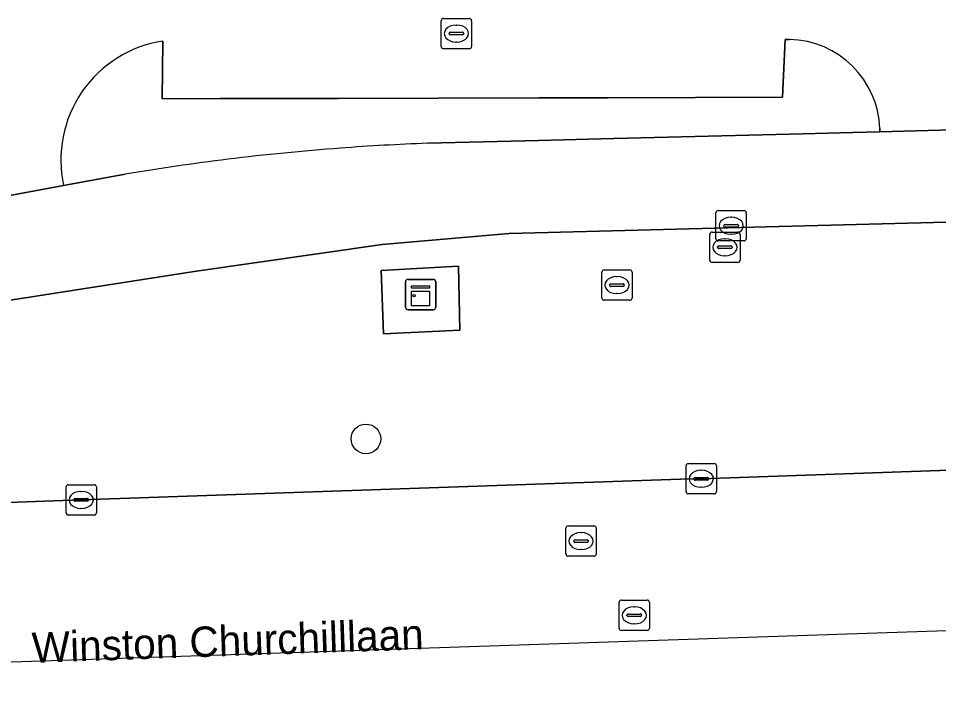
# Model space of a CAD drawing. Extents: x 160888 to 161385, y 386490 to 386908.
# Drawn here: x 161111.03 to 161141.39, y 386494.25 to 386516.39 of the extents above; entities that cross this region are included whole.
import ezdxf

# ---------------------------------------------------------------- set-up
doc = ezdxf.new("R2010")
doc.units = 0
for name, color, linetype in [('IMGEO_Berm_groen', 7, 'Continuous'), ('IMGEO_Boom', 7, 'Continuous'), ('IMGEO_Fietspad_gesloten', 7, 'Continuous'), ('IMGEO_Groenvoorziening', 7, 'Continuous'), ('IMGEO_Kast', 7, 'Continuous'), ('IMGEO_Kolk', 7, 'Continuous'), ('IMGEO_Openbare_ruimte_label', 7, 'Continuous'), ('IMGEO_Rijbaan_regionaal_gesloten', 7, 'Continuous'), ('IMGEO_Rioolput', 7, 'Continuous'), ('IMGEO_Voetgangersgebied_open', 7, 'Continuous'), ('IMGEO_Voetpad_open', 7, 'Continuous')]:
    doc.layers.add(name, color=color, linetype=linetype)

msp = doc.modelspace()

# ---------------------------------------------------------------- linework, layer by layer
at = {"layer": 'IMGEO_Berm_groen'}
msp.add_lwpolyline([(161167.964, 386510.348), (161127.225, 386509.29), (161123.035, 386508.931), (161116.836, 386508.035), (161109.839, 386506.955), (161110.084, 386500.399), (161113.106, 386500.507), (161132.874, 386501.189), (161133.563, 386501.204), (161154.024, 386501.918)], dxfattribs=at)
msp.add_lwpolyline([(161123.077, 386505.983), (161123.003, 386508.068), (161125.558, 386508.215), (161125.6, 386506.109)], close=True, dxfattribs=at)
at = {"layer": 'IMGEO_Boom'}
msp.add_circle((161122.501, 386502.519), 0.489, dxfattribs=at)
at = {"layer": 'IMGEO_Fietspad_gesloten'}
for points in [[(161142.637, 386512.729), (161139.461, 386512.648), (161138.561, 386512.625), (161136.913, 386512.583), (161130.684, 386512.424), (161128.205, 386512.361), (161124.527, 386512.267)], [(161106.833, 386506.491), (161109.839, 386506.955), (161116.836, 386508.035), (161123.035, 386508.931), (161127.225, 386509.29), (161167.964, 386510.348), (161215.734, 386511.569), (161215.758, 386511.159), (161222.805, 386511.284), (161237.753, 386511.488), (161259.697, 386511.429), (161267.164, 386511.376), (161306.097, 386509.668), (161311.73, 386509.285), (161311.776, 386509.705), (161313.071, 386509.592)], [(161114.554, 386511.246), (161112.524, 386510.872), (161110.624, 386510.522), (161110.357, 386510.473), (161109.295, 386510.286), (161107.767, 386510.044)]]:
    msp.add_lwpolyline(points, dxfattribs=at)
for centre, radius, start, end in [((161127.309, 386436.217), 76.101, 92.09478, 94.25602), ((161127.324, 386435.906), 76.412, 94.24984, 97.05235), ((161127.239, 386436.116), 76.193, 97.00834, 99.58319)]:
    msp.add_arc(centre, radius, start, end, dxfattribs=at)
at = {"layer": 'IMGEO_Groenvoorziening'}
for points in [[(161136.477, 386515.69), (161136.328, 386515.689), (161136.246, 386513.784), (161130.488, 386513.771), (161128.205, 386513.766), (161121.578, 386513.75), (161117.674, 386513.741), (161115.774, 386513.737), (161115.797, 386515.64)], [(161124.527, 386512.267), (161128.205, 386512.361), (161130.684, 386512.424), (161136.913, 386512.583), (161138.561, 386512.625), (161139.461, 386512.648)], [(161139.461, 386512.648), (161139.456, 386512.756)], [(161112.524, 386510.872), (161114.554, 386511.246)]]:
    msp.add_lwpolyline(points, dxfattribs=at)
for centre, radius, start, end in [((161116.404, 386511.716), 3.971, 98.7933, 192.2713), ((161136.411, 386512.644), 3.047, 2.1139, 88.7582), ((161127.309, 386436.217), 76.101, 92.09478, 94.25602), ((161127.324, 386435.906), 76.412, 94.24984, 97.05235), ((161127.239, 386436.116), 76.193, 97.00834, 99.58319)]:
    msp.add_arc(centre, radius, start, end, dxfattribs=at)
at = {"layer": 'IMGEO_Kast'}
for p, q in [((161123.804, 386506.855), (161123.804, 386507.696)), ((161123.804, 386507.696), (161123.804, 386506.855)), ((161123.879, 386507.78), (161124.72, 386507.78)), ((161124.72, 386507.78), (161123.879, 386507.78)), ((161124.804, 386507.705), (161124.804, 386506.864)), ((161124.804, 386506.864), (161124.804, 386507.705)), ((161124.729, 386506.78), (161123.888, 386506.78)), ((161123.888, 386506.78), (161124.729, 386506.78))]:
    msp.add_line(p, q, dxfattribs=at)
for points in [[(161123.999, 386507.57), (161124.599, 386507.57), (161124.599, 386507.485), (161123.999, 386507.485), (161123.999, 386507.57)], [(161123.999, 386507.395), (161124.599, 386507.395), (161124.599, 386506.906), (161123.999, 386506.906), (161123.999, 386507.395)]]:
    msp.add_lwpolyline(points, dxfattribs=at)
msp.add_circle((161124.083, 386507.244), 0.0377, dxfattribs=at)
for centre, start, end in [((161123.882, 386507.702), 92.4484, 184.2845), ((161123.882, 386507.702), 92.4484, 184.2845), ((161124.726, 386507.702), 2.4484, 94.2845), ((161124.726, 386507.702), 2.4484, 94.2845), ((161123.882, 386506.858), 182.4484, 274.2845), ((161123.882, 386506.858), 182.4484, 274.2845), ((161124.726, 386506.858), 272.4484, 4.2845), ((161124.726, 386506.858), 272.4484, 4.2845)]:
    msp.add_arc(centre, 0.0779, start, end, dxfattribs=at)
at = {"layer": 'IMGEO_Kolk'}
for p, q in [((161124.985, 386515.46), (161124.985, 386516.312)), ((161125.06, 386516.386), (161125.912, 386516.386)), ((161125.473, 386516.166), (161125.498, 386516.166)), ((161125.986, 386516.312), (161125.986, 386515.46)), ((161125.244, 386515.88), (161125.244, 386515.892)), ((161125.682, 386515.843), (161125.284, 386515.843)), ((161125.287, 386515.929), (161125.685, 386515.929)), ((161125.728, 386515.892), (161125.728, 386515.88)), ((161125.496, 386515.606), (161125.471, 386515.606)), ((161125.912, 386515.386), (161125.06, 386515.386)), ((161133.062, 386500.778), (161133.062, 386501.63)), ((161133.137, 386501.704), (161133.989, 386501.704)), ((161134.063, 386501.63), (161134.063, 386500.778)), ((161133.364, 386501.247), (161133.762, 386501.247)), ((161133.55, 386501.484), (161133.575, 386501.484)), ((161112.605, 386500.081), (161112.605, 386500.933)), ((161112.68, 386501.007), (161113.532, 386501.007)), ((161113.606, 386500.933), (161113.606, 386500.081)), ((161133.321, 386501.198), (161133.321, 386501.21)), ((161133.759, 386501.161), (161133.361, 386501.161)), ((161133.573, 386500.924), (161133.548, 386500.924)), ((161133.805, 386501.21), (161133.805, 386501.198)), ((161113.093, 386500.787), (161113.118, 386500.787)), ((161133.989, 386500.704), (161133.137, 386500.704)), ((161112.864, 386500.501), (161112.864, 386500.513)), ((161113.302, 386500.464), (161112.904, 386500.464)), ((161112.907, 386500.55), (161113.305, 386500.55)), ((161113.348, 386500.513), (161113.348, 386500.501)), ((161113.116, 386500.227), (161113.091, 386500.227)), ((161113.532, 386500.007), (161112.68, 386500.007))]:
    msp.add_line(p, q, dxfattribs=at)
for points in [[(161124.985, 386515.46), (161124.985, 386516.312)], [(161125.06, 386516.386), (161125.912, 386516.386)], [(161125.986, 386516.312), (161125.986, 386515.46)], [(161125.912, 386515.386), (161125.06, 386515.386)], [(161133.062, 386500.778), (161133.062, 386501.63)], [(161133.137, 386501.704), (161133.989, 386501.704)], [(161134.063, 386501.63), (161134.063, 386500.778)], [(161112.605, 386500.081), (161112.605, 386500.933)], [(161112.68, 386501.007), (161113.532, 386501.007)], [(161113.606, 386500.933), (161113.606, 386500.081)], [(161133.989, 386500.704), (161133.137, 386500.704)], [(161113.532, 386500.007), (161112.68, 386500.007)]]:
    msp.add_lwpolyline(points, dxfattribs=at)
for centre, radius, start, end in [((161125.062, 386516.31), 0.0765, 91.552, 178.448), ((161125.062, 386516.31), 0.0765, 91.552, 178.448), ((161125.91, 386516.31), 0.0765, 1.552, 88.448), ((161125.91, 386516.31), 0.0765, 1.552, 88.448), ((161125.284, 386515.889), 0.0403, 85.8775, 175.7526), ((161125.281, 386515.879), 0.0366, 178.938, 274.7102), ((161125.685, 386515.886), 0.043, 264.8664, 352.4533), ((161125.689, 386515.891), 0.0386, 1.7309, 96.639), ((161125.062, 386515.462), 0.0765, 181.552, 268.448), ((161125.062, 386515.462), 0.0765, 181.552, 268.448), ((161125.91, 386515.462), 0.0765, 271.552, 358.448), ((161125.91, 386515.462), 0.0765, 271.552, 358.448), ((161133.139, 386501.628), 0.0765, 91.552, 178.448), ((161133.139, 386501.628), 0.0765, 91.552, 178.448), ((161133.987, 386501.628), 0.0765, 1.552, 88.448), ((161133.987, 386501.628), 0.0765, 1.552, 88.448), ((161133.361, 386501.207), 0.0403, 85.8775, 175.7526), ((161133.766, 386501.209), 0.0386, 1.7309, 96.639), ((161112.682, 386500.931), 0.0765, 91.552, 178.448), ((161112.682, 386500.931), 0.0765, 91.552, 178.448), ((161113.53, 386500.931), 0.0765, 1.552, 88.448), ((161113.53, 386500.931), 0.0765, 1.552, 88.448), ((161133.358, 386501.197), 0.0366, 178.938, 274.7102), ((161133.762, 386501.204), 0.043, 264.8664, 352.4533), ((161133.139, 386500.78), 0.0765, 181.552, 268.448), ((161133.139, 386500.78), 0.0765, 181.552, 268.448), ((161133.987, 386500.78), 0.0765, 271.552, 358.448), ((161133.987, 386500.78), 0.0765, 271.552, 358.448), ((161112.904, 386500.51), 0.0403, 85.8775, 175.7526), ((161112.901, 386500.5), 0.0366, 178.938, 274.7102), ((161113.305, 386500.507), 0.043, 264.8664, 352.4533), ((161113.309, 386500.512), 0.0386, 1.7309, 96.639), ((161112.682, 386500.083), 0.0765, 181.552, 268.448), ((161112.682, 386500.083), 0.0765, 181.552, 268.448), ((161113.53, 386500.083), 0.0765, 271.552, 358.448), ((161113.53, 386500.083), 0.0765, 271.552, 358.448)]:
    msp.add_arc(centre, radius, start, end, dxfattribs=at)
for centre, major_axis, ratio, start_param, end_param in [((161125.472, 386515.886), (-0.387, 0.002), 0.722429, 4.712389, 7.853982), ((161125.497, 386515.886), (-0.39, 0.002), 0.717154, 1.570796, 4.712389), ((161133.549, 386501.204), (-0.387, 0.002), 0.722429, 4.712389, 7.853982), ((161133.574, 386501.204), (-0.39, 0.002), 0.717154, 1.570796, 4.712389), ((161113.092, 386500.507), (-0.387, 0.002), 0.722429, 4.712389, 7.853982), ((161113.117, 386500.507), (-0.39, 0.002), 0.717154, 1.570796, 4.712389)]:
    msp.add_ellipse(centre, major_axis=major_axis, ratio=ratio, start_param=start_param, end_param=end_param, dxfattribs=at)
at = {"layer": 'IMGEO_Rijbaan_regionaal_gesloten'}
for points in [[(161154.024, 386501.918), (161133.563, 386501.204), (161132.874, 386501.189), (161113.106, 386500.507), (161110.084, 386500.399), (161094.63, 386499.845), (161093.606, 386499.805), (161083.962, 386499.473), (161082.563, 386499.415), (161073.327, 386499.101), (161067.084, 386499.011), (161061.756, 386498.98)], [(161083.554, 386494.25), (161197.468, 386498.064)]]:
    msp.add_lwpolyline(points, dxfattribs=at)
at = {"layer": 'IMGEO_Rioolput'}
for p, q in [((161134.124, 386510.048), (161134.976, 386510.048)), ((161134.049, 386509.122), (161134.049, 386509.974)), ((161134.537, 386509.828), (161134.562, 386509.828)), ((161135.05, 386509.974), (161135.05, 386509.122)), ((161134.308, 386509.542), (161134.308, 386509.554)), ((161134.746, 386509.505), (161134.348, 386509.505)), ((161134.351, 386509.591), (161134.749, 386509.591)), ((161134.792, 386509.554), (161134.792, 386509.542)), ((161133.844, 386508.412), (161133.844, 386509.264)), ((161133.919, 386509.338), (161134.771, 386509.338)), ((161134.56, 386509.268), (161134.535, 386509.268)), ((161134.845, 386509.264), (161134.845, 386508.412)), ((161134.103, 386508.832), (161134.103, 386508.844)), ((161134.976, 386509.048), (161134.124, 386509.048)), ((161134.146, 386508.881), (161134.544, 386508.881)), ((161134.332, 386509.118), (161134.357, 386509.118)), ((161134.587, 386508.844), (161134.587, 386508.832)), ((161134.541, 386508.795), (161134.143, 386508.795)), ((161134.355, 386508.558), (161134.33, 386508.558)), ((161134.771, 386508.338), (161133.919, 386508.338)), ((161130.282, 386507.165), (161130.282, 386508.017)), ((161130.357, 386508.091), (161131.209, 386508.091)), ((161131.283, 386508.017), (161131.283, 386507.165)), ((161130.584, 386507.634), (161130.982, 386507.634)), ((161130.77, 386507.871), (161130.795, 386507.871)), ((161130.541, 386507.585), (161130.541, 386507.597)), ((161130.979, 386507.548), (161130.581, 386507.548)), ((161130.793, 386507.311), (161130.768, 386507.311)), ((161131.025, 386507.597), (161131.025, 386507.585)), ((161131.209, 386507.091), (161130.357, 386507.091)), ((161129.096, 386498.722), (161129.096, 386499.574)), ((161129.171, 386499.648), (161130.023, 386499.648)), ((161129.584, 386499.428), (161129.609, 386499.428)), ((161130.097, 386499.574), (161130.097, 386498.722)), ((161129.355, 386499.142), (161129.355, 386499.154)), ((161129.793, 386499.105), (161129.395, 386499.105)), ((161129.398, 386499.191), (161129.796, 386499.191)), ((161129.839, 386499.154), (161129.839, 386499.142)), ((161129.607, 386498.868), (161129.582, 386498.868)), ((161130.023, 386498.648), (161129.171, 386498.648)), ((161130.852, 386496.274), (161130.852, 386497.126)), ((161130.927, 386497.2), (161131.779, 386497.2)), ((161131.34, 386496.98), (161131.365, 386496.98)), ((161131.853, 386497.126), (161131.853, 386496.274)), ((161131.111, 386496.694), (161131.111, 386496.706)), ((161131.154, 386496.743), (161131.552, 386496.743)), ((161131.595, 386496.706), (161131.595, 386496.694)), ((161131.549, 386496.657), (161131.151, 386496.657)), ((161131.363, 386496.42), (161131.338, 386496.42)), ((161131.779, 386496.2), (161130.927, 386496.2))]:
    msp.add_line(p, q, dxfattribs=at)
for points in [[(161134.124, 386510.048), (161134.976, 386510.048)], [(161134.049, 386509.122), (161134.049, 386509.974)], [(161135.05, 386509.974), (161135.05, 386509.122)], [(161133.844, 386508.412), (161133.844, 386509.264)], [(161133.919, 386509.338), (161134.771, 386509.338)], [(161134.845, 386509.264), (161134.845, 386508.412)], [(161134.976, 386509.048), (161134.124, 386509.048)], [(161134.771, 386508.338), (161133.919, 386508.338)], [(161130.282, 386507.165), (161130.282, 386508.017)], [(161130.357, 386508.091), (161131.209, 386508.091)], [(161131.283, 386508.017), (161131.283, 386507.165)], [(161131.209, 386507.091), (161130.357, 386507.091)], [(161129.096, 386498.722), (161129.096, 386499.574)], [(161129.171, 386499.648), (161130.023, 386499.648)], [(161130.097, 386499.574), (161130.097, 386498.722)], [(161130.023, 386498.648), (161129.171, 386498.648)], [(161130.852, 386496.274), (161130.852, 386497.126)], [(161130.927, 386497.2), (161131.779, 386497.2)], [(161131.853, 386497.126), (161131.853, 386496.274)], [(161131.779, 386496.2), (161130.927, 386496.2)]]:
    msp.add_lwpolyline(points, dxfattribs=at)
for centre, radius, start, end in [((161134.126, 386509.972), 0.0765, 91.552, 178.448), ((161134.126, 386509.972), 0.0765, 91.552, 178.448), ((161134.974, 386509.972), 0.0765, 1.552, 88.448), ((161134.974, 386509.972), 0.0765, 1.552, 88.448), ((161134.348, 386509.551), 0.0403, 85.8775, 175.7526), ((161134.345, 386509.541), 0.0366, 178.938, 274.7102), ((161134.749, 386509.548), 0.043, 264.8664, 352.4533), ((161134.753, 386509.553), 0.0386, 1.7309, 96.639), ((161133.921, 386509.262), 0.0765, 91.552, 178.448), ((161133.921, 386509.262), 0.0765, 91.552, 178.448), ((161134.126, 386509.124), 0.0765, 181.552, 268.448), ((161134.126, 386509.124), 0.0765, 181.552, 268.448), ((161134.769, 386509.262), 0.0765, 1.552, 88.448), ((161134.769, 386509.262), 0.0765, 1.552, 88.448), ((161134.974, 386509.124), 0.0765, 271.552, 358.448), ((161134.974, 386509.124), 0.0765, 271.552, 358.448), ((161134.143, 386508.841), 0.0403, 85.8775, 175.7526), ((161134.14, 386508.831), 0.0366, 178.938, 274.7102), ((161134.544, 386508.838), 0.043, 264.8664, 352.4533), ((161134.548, 386508.843), 0.0386, 1.7309, 96.639), ((161133.921, 386508.414), 0.0765, 181.552, 268.448), ((161133.921, 386508.414), 0.0765, 181.552, 268.448), ((161134.769, 386508.414), 0.0765, 271.552, 358.448), ((161134.769, 386508.414), 0.0765, 271.552, 358.448), ((161130.359, 386508.015), 0.0765, 91.552, 178.448), ((161130.359, 386508.015), 0.0765, 91.552, 178.448), ((161131.207, 386508.015), 0.0765, 1.552, 88.448), ((161131.207, 386508.015), 0.0765, 1.552, 88.448), ((161130.581, 386507.594), 0.0403, 85.8775, 175.7526), ((161130.986, 386507.596), 0.0386, 1.7309, 96.639), ((161130.578, 386507.584), 0.0366, 178.938, 274.7102), ((161130.982, 386507.591), 0.043, 264.8664, 352.4533), ((161130.359, 386507.167), 0.0765, 181.552, 268.448), ((161130.359, 386507.167), 0.0765, 181.552, 268.448), ((161131.207, 386507.167), 0.0765, 271.552, 358.448), ((161131.207, 386507.167), 0.0765, 271.552, 358.448), ((161129.173, 386499.572), 0.0765, 91.552, 178.448), ((161129.173, 386499.572), 0.0765, 91.552, 178.448), ((161130.021, 386499.572), 0.0765, 1.552, 88.448), ((161130.021, 386499.572), 0.0765, 1.552, 88.448), ((161129.395, 386499.151), 0.0403, 85.8775, 175.7526), ((161129.392, 386499.141), 0.0366, 178.938, 274.7102), ((161129.796, 386499.148), 0.043, 264.8664, 352.4533), ((161129.8, 386499.153), 0.0386, 1.7309, 96.639), ((161129.173, 386498.724), 0.0765, 181.552, 268.448), ((161129.173, 386498.724), 0.0765, 181.552, 268.448), ((161130.021, 386498.724), 0.0765, 271.552, 358.448), ((161130.021, 386498.724), 0.0765, 271.552, 358.448), ((161130.929, 386497.124), 0.0765, 91.552, 178.448), ((161130.929, 386497.124), 0.0765, 91.552, 178.448), ((161131.777, 386497.124), 0.0765, 1.552, 88.448), ((161131.777, 386497.124), 0.0765, 1.552, 88.448), ((161131.151, 386496.703), 0.0403, 85.8775, 175.7526), ((161131.148, 386496.693), 0.0366, 178.938, 274.7102), ((161131.552, 386496.7), 0.043, 264.8664, 352.4533), ((161131.556, 386496.705), 0.0386, 1.7309, 96.639), ((161130.929, 386496.276), 0.0765, 181.552, 268.448), ((161130.929, 386496.276), 0.0765, 181.552, 268.448), ((161131.777, 386496.276), 0.0765, 271.552, 358.448), ((161131.777, 386496.276), 0.0765, 271.552, 358.448)]:
    msp.add_arc(centre, radius, start, end, dxfattribs=at)
for centre, major_axis, ratio, start_param, end_param in [((161134.536, 386509.548), (-0.387, 0.002), 0.722429, 4.712389, 7.853982), ((161134.561, 386509.548), (-0.39, 0.002), 0.717154, 1.570796, 4.712389), ((161134.331, 386508.838), (-0.387, 0.002), 0.722429, 4.712389, 7.853982), ((161134.356, 386508.838), (-0.39, 0.002), 0.717154, 1.570796, 4.712389), ((161130.769, 386507.591), (-0.387, 0.002), 0.722429, 4.712389, 7.853982), ((161130.794, 386507.591), (-0.39, 0.002), 0.717154, 1.570796, 4.712389), ((161129.583, 386499.148), (-0.387, 0.002), 0.722429, 4.712389, 7.853982), ((161129.608, 386499.148), (-0.39, 0.002), 0.717154, 1.570796, 4.712389), ((161131.339, 386496.7), (-0.387, 0.002), 0.722429, 4.712389, 7.853982), ((161131.364, 386496.7), (-0.39, 0.002), 0.717154, 1.570796, 4.712389)]:
    msp.add_ellipse(centre, major_axis=major_axis, ratio=ratio, start_param=start_param, end_param=end_param, dxfattribs=at)
at = {"layer": 'IMGEO_Voetgangersgebied_open'}
for points in [[(161115.797, 386515.64), (161115.774, 386513.737), (161117.674, 386513.741), (161121.578, 386513.75), (161128.205, 386513.766), (161130.488, 386513.771), (161136.246, 386513.784), (161136.328, 386515.689), (161136.477, 386515.69)], [(161139.456, 386512.756), (161139.461, 386512.648), (161142.637, 386512.729)], [(161109.295, 386510.286), (161110.357, 386510.473), (161110.624, 386510.522), (161112.524, 386510.872)]]:
    msp.add_lwpolyline(points, dxfattribs=at)
for centre, radius, start, end in [((161116.404, 386511.716), 3.971, 98.7933, 192.2713), ((161136.411, 386512.644), 3.047, 2.1139, 88.7582)]:
    msp.add_arc(centre, radius, start, end, dxfattribs=at)
at = {"layer": 'IMGEO_Voetpad_open'}
msp.add_lwpolyline([(161123.077, 386505.983), (161125.6, 386506.109), (161125.558, 386508.215), (161123.003, 386508.068)], close=True, dxfattribs=at)

# ---------------------------------------------------------------- texts
at = {"layer": 'IMGEO_Openbare_ruimte_label'}
msp.add_text('Winston Churchilllaan', height=1, rotation=2.0065, dxfattribs=at).set_placement((161111.494, 386495.13))

doc.saveas('drawing.dxf')
